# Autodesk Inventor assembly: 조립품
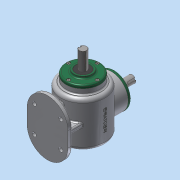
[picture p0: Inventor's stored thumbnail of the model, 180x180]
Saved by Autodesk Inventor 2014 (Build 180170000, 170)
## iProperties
Created: 2023-01
Part Number: 조립품
Document SubType Name: Assembly
Designer: dg
Mass: 2600.27 g
Surface Area: 1982.95 cm^2
Volume: 583.412 cm^3
Density: 4.457 g/cm^3
Author: dg
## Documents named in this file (14)
- C:\Users\dg\Desktop\730106V1024\조립품.iam
- C:\Users\dg\Desktop\730106V1024\M4.ipt
- C:\Users\dg\Desktop\730106V1024\메인 베벨기어.ipt
- C:\Users\dg\Desktop\730106V1024\메인 축.ipt
- 메인 축.ipt
- C:\Users\dg\Desktop\730106V1024\베어링 6203.ipt
- C:\Users\dg\Desktop\730106V1024\서브 베벨기어.ipt
- C:\Users\dg\Desktop\730106V1024\서브 축.ipt
- 서브 축.ipt
- C:\Users\dg\Desktop\730106V1024\오일실 17 32 8.ipt
- C:\Users\dg\Desktop\730106V1024\커버.ipt
- C:\Users\dg\Desktop\730106V1024\키 4x4.ipt
- C:\Users\dg\Desktop\730106V1024\키 5x5.ipt
- C:\Users\dg\Desktop\730106V1024\본체.ipt
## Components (8 placed, 1 different names)
1. M4:1
2. M4:3
3. M4:4
4. M4:5
5. M4:2
6. M4:6
7. M4:7
8. M4:8
